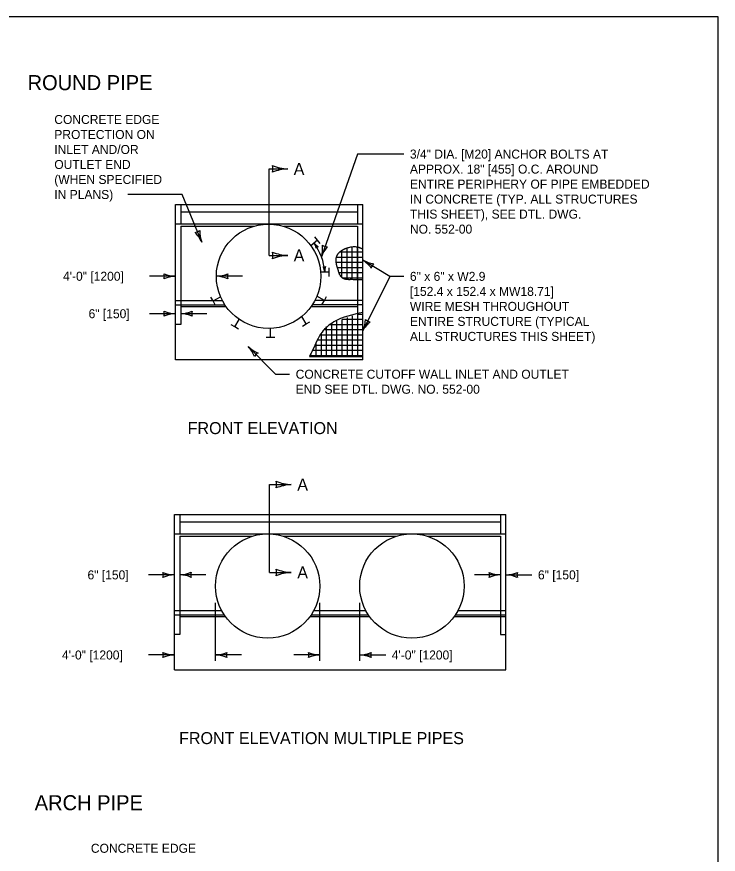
# Model space of a CAD drawing. Extents: x 49991.4 to 50021, y 49987.6 to 50011.4.
# Drawn here: x 50003.94 to 50008.61, y 50005.68 to 50011.26 of the extents above; entities that cross this region are included whole.
import ezdxf

# ---------------------------------------------------------------- set-up
doc = ezdxf.new("R2010")
doc.units = 0
for name, color, linetype in [('Level 1', 7, 'Continuous'), ('Level 2', 7, 'Continuous'), ('Level 3', 7, 'Continuous'), ('Level 4', 7, 'Continuous'), ('Level 6', 7, 'Continuous')]:
    doc.layers.add(name, color=color, linetype=linetype)

msp = doc.modelspace()

# ---------------------------------------------------------------- linework, layer by layer
at = {"layer": 'Level 1'}
for p, q in [((50005.0004, 50008.9757), (50005.0004, 50010.0112)), ((50005.0004, 50010.0112), (50006.2479, 50010.0112)), ((50006.2479, 50008.9757), (50006.2479, 50010.0112)), ((50005.9467, 50009.7742), (50005.9282, 50009.7964)), ((50005.9467, 50009.7742), (50005.9026, 50009.7372)), ((50005.9651, 50009.7524), (50005.9467, 50009.7742)), ((50006.096, 50009.6959), (50006.2479, 50009.6959)), ((50006.1085, 50009.5263), (50006.1085, 50009.7047)), ((50006.143, 50009.5136), (50006.143, 50009.7209)), ((50006.1775, 50009.5132), (50006.1775, 50009.7282)), ((50006.212, 50009.513), (50006.212, 50009.727)), ((50006.0689, 50009.6269), (50006.2479, 50009.6269)), ((50006.0712, 50009.6614), (50006.2479, 50009.6614)), ((50005.0004, 50009.4903), (50005.0004, 50009.6004)), ((50006.0249, 50009.5615), (50006.0249, 50009.5901)), ((50006.0772, 50009.5924), (50006.2479, 50009.5924)), ((50006.0249, 50009.5615), (50005.9674, 50009.5614)), ((50006.0249, 50009.5327), (50006.0249, 50009.5615)), ((50006.0881, 50009.5579), (50006.2479, 50009.5579)), ((50006.1124, 50009.5234), (50006.2479, 50009.5234)), ((50005.0004, 50009.3729), (50005.3126, 50009.3729)), ((50005.2511, 50009.3689), (50005.2367, 50009.3938)), ((50005.2511, 50009.3689), (50005.3009, 50009.3976)), ((50005.2655, 50009.3442), (50005.2511, 50009.3689)), ((50005.9295, 50009.3737), (50006.2479, 50009.3737)), ((50005.9922, 50009.3728), (50005.9424, 50009.4015)), ((50005.9779, 50009.3481), (50005.9922, 50009.3728)), ((50005.9922, 50009.3728), (50006.0066, 50009.3977)), ((50005.0004, 50009.3441), (50005.3294, 50009.3441)), ((50005.9131, 50009.3454), (50006.2479, 50009.3454)), ((50005.3965, 50009.1966), (50005.4252, 50009.2463)), ((50005.8713, 50009.2164), (50005.8427, 50009.266)), ((50006.074, 50009.2352), (50006.074, 50009.0059)), ((50006.1085, 50009.2466), (50006.1085, 50009.0059)), ((50006.1109, 50009.2474), (50006.2479, 50009.2474)), ((50006.143, 50009.258), (50006.143, 50009.0059)), ((50006.1775, 50009.2694), (50006.1775, 50009.0059)), ((50006.212, 50009.2808), (50006.212, 50009.0059)), ((50006.2152, 50009.2819), (50006.2479, 50009.2819)), ((50005.3965, 50009.1966), (50005.3715, 50009.211)), ((50005.4214, 50009.1822), (50005.3965, 50009.1966)), ((50005.6325, 50009.1287), (50005.6325, 50009.1862)), ((50005.8464, 50009.2019), (50005.8713, 50009.2164)), ((50005.8713, 50009.2164), (50005.8964, 50009.2307)), ((50006.005, 50009.1978), (50006.005, 50009.0059)), ((50006.0234, 50009.2129), (50006.2479, 50009.2129)), ((50006.0395, 50009.2225), (50006.0395, 50009.0059)), ((50005.6037, 50009.1287), (50005.6325, 50009.1287)), ((50005.6325, 50009.1287), (50005.6612, 50009.1287)), ((50005.9675, 50009.1439), (50006.2479, 50009.1439)), ((50005.9705, 50009.1494), (50005.9705, 50009.0059)), ((50005.988, 50009.1784), (50006.2479, 50009.1784)), ((50005.9312, 50009.0749), (50006.2479, 50009.0749)), ((50005.936, 50009.0842), (50005.936, 50009.0059)), ((50005.9491, 50009.1094), (50006.2479, 50009.1094)), ((50005.9137, 50009.0404), (50006.2479, 50009.0404)), ((50006.2479, 50008.9757), (50005.0004, 50008.9757)), ((50005.8933, 50008.9999), (50006.2479, 50008.9999)), ((50005.8964, 50009.0059), (50006.2479, 50009.0059)), ((50004.9935, 50007.9456), (50007.2009, 50007.9456)), ((50004.9935, 50006.9101), (50004.9935, 50007.9456)), ((50007.2009, 50006.9101), (50007.2009, 50007.9456)), ((50004.9935, 50007.3073), (50005.3073, 50007.3073)), ((50005.9225, 50007.3073), (50006.2672, 50007.3073)), ((50006.8824, 50007.3073), (50007.2009, 50007.3073)), ((50004.9935, 50007.2785), (50005.3243, 50007.2785)), ((50005.9055, 50007.2785), (50006.2842, 50007.2785)), ((50006.8655, 50007.2785), (50007.2009, 50007.2785)), ((50004.9935, 50006.9101), (50007.2009, 50006.9101))]:
    msp.add_line(p, q, dxfattribs=at)
msp.add_lwpolyline([(50008.6146, 50011.2628), (50000.3356, 50011.2628), (50000.3356, 50000.0624), (50008.6146, 50000.0624)], close=True, dxfattribs=at)
for centre in [(50005.6208, 50009.5337), (50005.6149, 50007.4693), (50006.5748, 50007.4693)]:
    msp.add_circle(centre, 0.3476, dxfattribs=at)
msp.add_open_spline([(50006.2479, 50009.7123), (50006.2468, 50009.7131), (50006.2456, 50009.7138), (50006.2444, 50009.7146), (50006.2433, 50009.7154), (50006.2421, 50009.716), (50006.2409, 50009.7167), (50006.2385, 50009.7181), (50006.236, 50009.7193), (50006.2334, 50009.7204), (50006.2283, 50009.7228), (50006.2231, 50009.7244), (50006.2175, 50009.7258), (50006.2061, 50009.7285), (50006.1944, 50009.7294), (50006.1829, 50009.7286), (50006.1711, 50009.7278), (50006.1592, 50009.7259), (50006.1475, 50009.7223), (50006.1416, 50009.7205), (50006.136, 50009.7186), (50006.1305, 50009.7162), (50006.1277, 50009.715), (50006.125, 50009.7138), (50006.1223, 50009.7124), (50006.121, 50009.7118), (50006.1197, 50009.7111), (50006.1184, 50009.7104), (50006.1171, 50009.7097), (50006.1158, 50009.709), (50006.1145, 50009.7083), (50006.1122, 50009.707), (50006.11, 50009.7056), (50006.1078, 50009.7043), (50006.1055, 50009.7029), (50006.1034, 50009.7014), (50006.1013, 50009.6999), (50006.0971, 50009.697), (50006.0932, 50009.6937), (50006.0895, 50009.6902), (50006.0859, 50009.6867), (50006.0826, 50009.683), (50006.0798, 50009.6788), (50006.0784, 50009.6768), (50006.077, 50009.6747), (50006.0759, 50009.6725), (50006.0753, 50009.6714), (50006.0747, 50009.6702), (50006.0742, 50009.6691), (50006.0739, 50009.6685), (50006.0737, 50009.6679), (50006.0734, 50009.6674), (50006.0732, 50009.6668), (50006.0729, 50009.6662), (50006.0727, 50009.6656), (50006.0721, 50009.6641), (50006.0716, 50009.6626), (50006.0711, 50009.661), (50006.0706, 50009.6595), (50006.0702, 50009.6579), (50006.0699, 50009.6563), (50006.0692, 50009.6532), (50006.0687, 50009.6501), (50006.0684, 50009.6469), (50006.0679, 50009.6405), (50006.068, 50009.634), (50006.0688, 50009.6276), (50006.0697, 50009.6211), (50006.0709, 50009.6146), (50006.0726, 50009.6082), (50006.0734, 50009.605), (50006.0742, 50009.6019), (50006.0752, 50009.5987), (50006.0762, 50009.5956), (50006.0772, 50009.5925), (50006.0782, 50009.5894), (50006.0787, 50009.5878), (50006.0792, 50009.5863), (50006.0797, 50009.5847), (50006.0802, 50009.5831), (50006.0807, 50009.5815), (50006.0811, 50009.5799), (50006.0821, 50009.5767), (50006.083, 50009.5735), (50006.0839, 50009.5703), (50006.0858, 50009.564), (50006.0881, 50009.5577), (50006.0905, 50009.5515), (50006.0928, 50009.5454), (50006.0961, 50009.5399), (50006.1001, 50009.5347), (50006.1022, 50009.532), (50006.1044, 50009.5297), (50006.1069, 50009.5276), (50006.1082, 50009.5265), (50006.1095, 50009.5254), (50006.1109, 50009.5244), (50006.1117, 50009.5239), (50006.1124, 50009.5234), (50006.1131, 50009.523), (50006.1135, 50009.5227), (50006.1139, 50009.5225), (50006.1142, 50009.5223), (50006.1146, 50009.522), (50006.115, 50009.5218), (50006.1154, 50009.5216), (50006.1165, 50009.521), (50006.1176, 50009.5204), (50006.1188, 50009.5198), (50006.1199, 50009.5193), (50006.121, 50009.5188), (50006.1222, 50009.5183), (50006.1244, 50009.5174), (50006.1266, 50009.5166), (50006.129, 50009.516), (50006.1335, 50009.5148), (50006.138, 50009.5139), (50006.1426, 50009.5136), (50006.1472, 50009.5133), (50006.1518, 50009.5131), (50006.1564, 50009.5131), (50006.161, 50009.5131), (50006.1656, 50009.5132), (50006.1702, 50009.5132), (50006.1961, 50009.5131), (50006.222, 50009.513), (50006.2479, 50009.5129)], degree=3, dxfattribs=at)
msp.add_spline([(50006.2479, 50009.2927), (50006.055, 50009.2289), (50005.977, 50009.1613), (50005.9138, 50009.0406), (50005.8933, 50008.9999)], degree=3, dxfattribs=at)
at = {"layer": 'Level 3'}
for p, q in [((50006.2132, 50010.3477), (50005.9728, 50009.6631)), ((50006.5217, 50010.3477), (50006.2132, 50010.3477)), ((50005.0443, 50010.0784), (50004.6827, 50010.0784)), ((50005.1752, 50009.7615), (50005.0443, 50010.0784)), ((50006.4278, 50009.5329), (50006.2479, 50009.6417)), ((50005.0004, 50009.5337), (50004.827, 50009.5337)), ((50005.4467, 50009.5337), (50005.2732, 50009.5337)), ((50006.4278, 50009.5329), (50006.2479, 50009.17)), ((50006.5217, 50009.5329), (50006.4278, 50009.5329)), ((50005.0004, 50009.2841), (50004.827, 50009.2841)), ((50005.2097, 50009.2842), (50005.0363, 50009.2842)), ((50005.4854, 50009.0648), (50005.666, 50008.8808)), ((50005.666, 50008.8808), (50005.761, 50008.8808)), ((50004.9935, 50007.5439), (50004.8201, 50007.5439)), ((50005.2028, 50007.5443), (50005.0294, 50007.5443)), ((50007.165, 50007.5439), (50006.9916, 50007.5439)), ((50007.2009, 50007.5439), (50007.3743, 50007.5439)), ((50005.2674, 50006.9701), (50005.2674, 50007.3581)), ((50005.9623, 50006.9701), (50005.9623, 50007.3581)), ((50006.2274, 50006.9701), (50006.2274, 50007.3581)), ((50004.9935, 50007.0101), (50004.8201, 50007.0101)), ((50005.4408, 50007.0101), (50005.2674, 50007.0101)), ((50005.9623, 50007.0101), (50005.7889, 50007.0101)), ((50006.2274, 50007.0101), (50006.4008, 50007.0101))]:
    msp.add_line(p, q, dxfattribs=at)
for centre, radius, start, end in [((50005.76, 50010.5449), 0.2964, 247.456, 267.6395), ((50005.5768, 50010.2487), 0.073, 342.1388, 17.8612), ((50005.7631, 50009.9384), 0.3107, 92.8273, 112.0772), ((50005.1268, 50009.8802), 0.0548, 274.3386, 310.061), ((50004.9641, 50009.6629), 0.233, 25.0271, 44.277), ((50005.3843, 50009.837), 0.2223, 179.6558, 199.8393), ((50005.8351, 50009.6956), 0.1065, 13.6086, 33.7921), ((50006.0104, 50009.8251), 0.1116, 218.9799, 238.2298), ((50005.6208, 50009.5337), 0.375, 4.2501, 36.1526), ((50005.7476, 50009.7227), 0.233, 345.1641, 4.4139), ((50006.0117, 50009.7853), 0.0548, 234.4756, 270.1979), ((50005.76, 50009.9685), 0.2964, 247.456, 267.6395), ((50005.5768, 50009.6723), 0.073, 342.1388, 17.8612), ((50005.9599, 50009.7053), 0.0262, 108.2914, 144.0138), ((50006.1817, 50009.587), 0.2223, 139.7928, 159.9763), ((50005.7631, 50009.362), 0.3107, 92.8273, 112.0772), ((50006.1251, 50009.4564), 0.2223, 36.2865, 56.47), ((50006.3585, 50009.8468), 0.233, 241.6578, 260.9076), ((50005.9903, 50009.6227), 0.0262, 256.3763, 292.0987), ((50005.884, 50009.5477), 0.1116, 7.0648, 26.3146), ((50006.1013, 50009.5649), 0.1065, 161.6935, 181.877), ((50006.3576, 50009.5754), 0.0548, 130.9693, 166.6916), ((50005.0096, 50009.7558), 0.2223, 247.456, 267.6395), ((50004.8722, 50009.5337), 0.0548, 342.1388, 17.8612), ((50005.0119, 50009.301), 0.233, 92.8273, 112.0772), ((50005.2617, 50009.7664), 0.233, 272.8273, 292.0772), ((50005.2641, 50009.3116), 0.2223, 67.456, 87.6395), ((50005.4014, 50009.5337), 0.0548, 162.1388, 197.8612), ((50005.0096, 50009.5062), 0.2223, 247.456, 267.6395), ((50004.8722, 50009.2841), 0.0548, 342.1388, 17.8612), ((50005.0248, 50009.5169), 0.233, 272.8273, 292.0772), ((50005.1645, 50009.2842), 0.0548, 162.1388, 197.8612), ((50005.0119, 50009.0514), 0.233, 92.8273, 112.0772), ((50005.0271, 50009.0621), 0.2223, 67.456, 87.6395), ((50006.0343, 50009.263), 0.233, 336.4612, 355.7111), ((50006.3048, 50009.2848), 0.0548, 225.7727, 261.4951), ((50006.4429, 50009.0631), 0.2223, 131.0899, 151.2734), ((50005.3205, 50008.9157), 0.2223, 21.9217, 42.1052), ((50005.6434, 50009.236), 0.233, 227.293, 246.5429), ((50005.5752, 50008.9733), 0.0548, 116.6045, 152.3269), ((50005.784, 50008.4414), 0.2964, 247.456, 267.6395), ((50005.6008, 50008.1452), 0.073, 342.1388, 17.8612), ((50005.7871, 50007.8349), 0.3107, 92.8273, 112.0772), ((50005.0027, 50007.766), 0.2223, 247.456, 267.6395), ((50004.8653, 50007.5439), 0.0548, 342.1388, 17.8612), ((50005.0179, 50007.777), 0.233, 272.8273, 292.0772), ((50005.1576, 50007.5443), 0.0548, 162.1388, 197.8612), ((50005.784, 50007.8563), 0.2964, 247.456, 267.6395), ((50005.6008, 50007.5601), 0.073, 342.1388, 17.8612), ((50007.1742, 50007.766), 0.2223, 247.456, 267.6395), ((50007.0368, 50007.5439), 0.0548, 342.1388, 17.8612), ((50007.1894, 50007.7766), 0.233, 272.8273, 292.0772), ((50007.3291, 50007.5439), 0.0548, 162.1388, 197.8612), ((50005.005, 50007.3112), 0.233, 92.8273, 112.0772), ((50005.0202, 50007.3222), 0.2223, 67.456, 87.6395), ((50005.7871, 50007.2498), 0.3107, 92.8273, 112.0772), ((50007.1765, 50007.3112), 0.233, 92.8273, 112.0772), ((50007.1917, 50007.3218), 0.2223, 67.456, 87.6395), ((50005.0027, 50007.2322), 0.2223, 247.456, 267.6395), ((50004.8653, 50007.0101), 0.0548, 342.1388, 17.8612), ((50005.005, 50006.7774), 0.233, 92.8273, 112.0772), ((50005.2559, 50007.2428), 0.233, 272.8273, 292.0772), ((50005.2582, 50006.788), 0.2223, 67.456, 87.6395), ((50005.3956, 50007.0101), 0.0548, 162.1388, 197.8612), ((50005.9715, 50007.2322), 0.2223, 247.456, 267.6395), ((50005.8341, 50007.0101), 0.0548, 342.1388, 17.8612), ((50005.9738, 50006.7774), 0.233, 92.8273, 112.0772), ((50006.2159, 50007.2428), 0.233, 272.8273, 292.0772), ((50006.2182, 50006.788), 0.2223, 67.456, 87.6395), ((50006.3556, 50007.0101), 0.0548, 162.1388, 197.8612)]:
    msp.add_arc(centre, radius, start, end, dxfattribs=at)
at = {"layer": 'Level 4'}
for p, q in [((50005.0363, 50010.0112), (50005.0363, 50009.8824)), ((50005.0363, 50009.9626), (50006.212, 50009.9626)), ((50006.212, 50010.0112), (50006.212, 50009.8825)), ((50005.0004, 50009.8824), (50006.2479, 50009.8825)), ((50005.0363, 50009.8672), (50005.0363, 50009.2123)), ((50005.0363, 50009.8672), (50005.5229, 50009.8672)), ((50005.7215, 50009.8664), (50006.212, 50009.8664)), ((50006.212, 50009.8664), (50006.212, 50009.2123)), ((50005.0363, 50009.3326), (50005.3373, 50009.3326)), ((50005.9049, 50009.3332), (50006.212, 50009.3332)), ((50005.0363, 50009.2123), (50005.0004, 50009.2123)), ((50006.212, 50009.2123), (50006.2479, 50009.2123)), ((50005.0294, 50007.9456), (50005.0294, 50007.8169)), ((50005.0294, 50007.897), (50007.165, 50007.897)), ((50007.165, 50007.9456), (50007.165, 50007.8169)), ((50004.9935, 50007.8169), (50007.2009, 50007.8169)), ((50005.0294, 50007.8016), (50005.0294, 50007.1467)), ((50005.0294, 50007.8016), (50005.5129, 50007.8016)), ((50005.7169, 50007.8016), (50006.4728, 50007.8016)), ((50006.6768, 50007.8016), (50007.165, 50007.8016)), ((50007.165, 50007.8016), (50007.165, 50007.1467)), ((50005.0294, 50007.267), (50005.3321, 50007.267)), ((50005.8976, 50007.267), (50006.2921, 50007.267)), ((50006.8576, 50007.267), (50007.2009, 50007.267)), ((50005.0294, 50007.1467), (50004.9935, 50007.1467)), ((50007.165, 50007.1467), (50007.2009, 50007.1467))]:
    msp.add_line(p, q, dxfattribs=at)
at = {"layer": 'Level 6'}
for p, q in [((50005.6241, 50009.6723), (50005.6241, 50010.2487)), ((50005.6241, 50010.2487), (50005.7478, 50010.2487)), ((50005.6241, 50009.6723), (50005.7478, 50009.6723)), ((50005.6265, 50007.5601), (50005.6265, 50008.1452)), ((50005.6265, 50008.1452), (50005.7718, 50008.1452)), ((50005.6265, 50007.5601), (50005.7718, 50007.5601))]:
    msp.add_line(p, q, dxfattribs=at)

# ---------------------------------------------------------------- texts
at = {"layer": 'Level 2'}
for s, height, p in [('ROUND PIPE', 0.1, (50004.0158, 50010.7737)), ('CONCRETE EDGE', 0.06, (50004.1939, 50010.5484)), ('PROTECTION ON', 0.06, (50004.1939, 50010.4484)), ('INLET AND/OR', 0.06, (50004.1939, 50010.3484)), ('3/4" DIA. [M20] ANCHOR BOLTS AT ', 0.06, (50006.5617, 50010.3177)), ('OUTLET END', 0.06, (50004.1939, 50010.2484)), ('A', 0.08, (50005.7878, 50010.2087)), ('APPROX. 18" [455] O.C. AROUND ', 0.06, (50006.5617, 50010.2177)), ('(WHEN SPECIFIED', 0.06, (50004.1939, 50010.1484)), ('ENTIRE PERIPHERY OF PIPE EMBEDDED ', 0.06, (50006.5617, 50010.1177)), ('IN PLANS)', 0.06, (50004.1939, 50010.0484)), ('IN CONCRETE (TYP. ALL STRUCTURES ', 0.06, (50006.5617, 50010.0177)), ('THIS SHEET), SEE DTL. DWG. ', 0.06, (50006.5617, 50009.9177)), ('NO. 552-00', 0.06, (50006.5617, 50009.8177)), ('A', 0.08, (50005.7878, 50009.6323)), ('4\'-0" [1200]', 0.06, (50004.2519, 50009.5037)), ('6" x 6" x W2.9  ', 0.06, (50006.5617, 50009.5029)), ('[152.4 x 152.4 x MW18.71]', 0.06, (50006.5617, 50009.4029)), ('WIRE MESH THROUGHOUT', 0.06, (50006.5617, 50009.3029)), ('6" [150]', 0.06, (50004.422, 50009.2541)), ('ENTIRE STRUCTURE (TYPICAL ', 0.06, (50006.5617, 50009.2029)), ('ALL STRUCTURES THIS SHEET)', 0.06, (50006.5617, 50009.1029)), ('CONCRETE CUTOFF WALL INLET AND OUTLET', 0.06, (50005.801, 50008.8508)), ('END SEE DTL. DWG. NO. 552-00', 0.06, (50005.801, 50008.7508)), ('FRONT ELEVATION', 0.08, (50005.082, 50008.4818)), ('A', 0.08, (50005.8118, 50008.1052)), ('6" [150]', 0.06, (50004.4151, 50007.5139)), ('A', 0.08, (50005.8118, 50007.5201)), ('6" [150]', 0.06, (50007.4143, 50007.5139)), ('4\'-0" [1200]', 0.06, (50004.245, 50006.9801)), ('4\'-0" [1200]', 0.06, (50006.4408, 50006.9801)), ('FRONT ELEVATION MULTIPLE PIPES', 0.08, (50005.0249, 50006.4162)), ('ARCH PIPE', 0.1, (50004.0634, 50005.976)), ('CONCRETE EDGE', 0.06, (50004.4374, 50005.6921))]:
    msp.add_text(s, height=height, dxfattribs=at).set_placement(p)

doc.saveas('drawing.dxf')
